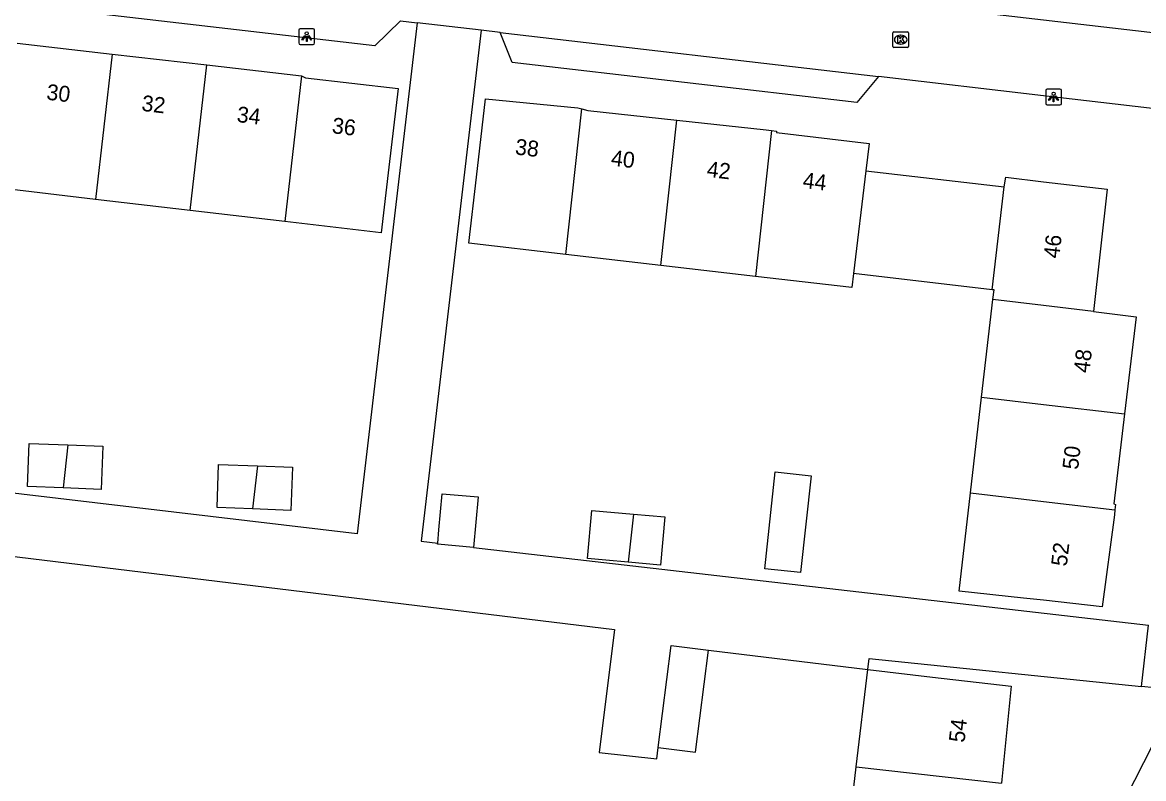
# Model space of a CAD drawing. Extents: x 161243 to 161752, y 384138 to 384885.
# Drawn here: x 161435.4 to 161506.3, y 384369.4 to 384417.2 of the extents above; entities that cross this region are included whole.
import ezdxf

# ---------------------------------------------------------------- set-up
doc = ezdxf.new("R2010")
doc.units = 0
for name, color, linetype in [('IMGEO_Kolk', 7, 'Continuous'), ('IMGEO_Lichtpunt', 7, 'Continuous'), ('IMGEO_Pand', 7, 'Continuous'), ('IMGEO_Pand_nummerreeks', 7, 'Continuous'), ('IMGEO_Parkeervlak_open', 7, 'Continuous'), ('IMGEO_Rijbaan_lokaal_open', 7, 'Continuous')]:
    doc.layers.add(name, color=color, linetype=linetype)

msp = doc.modelspace()

# ---------------------------------------------------------------- linework, layer by layer
at = {"layer": 'IMGEO_Kolk'}
for p, q in [((161490.463, 384415.656), (161490.463, 384416.508)), ((161490.538, 384416.582), (161491.39, 384416.582)), ((161490.951, 384416.362), (161490.976, 384416.362)), ((161491.464, 384416.508), (161491.464, 384415.656)), ((161491.39, 384415.582), (161490.538, 384415.582)), ((161490.974, 384415.802), (161490.949, 384415.802))]:
    msp.add_line(p, q, dxfattribs=at)
for points in [[(161490.463, 384415.656), (161490.463, 384416.508)], [(161490.538, 384416.582), (161491.39, 384416.582)], [(161490.784, 384416.282), (161490.907, 384416.282), (161490.907, 384416.131), (161491.037, 384416.282), (161491.201, 384416.282), (161491.055, 384416.131), (161491.208, 384415.882), (161491.056, 384415.882), (161490.971, 384416.046), (161490.907, 384415.979), (161490.907, 384415.882), (161490.784, 384415.882), (161490.784, 384416.282)], [(161491.464, 384416.508), (161491.464, 384415.656)], [(161491.39, 384415.582), (161490.538, 384415.582)]]:
    msp.add_lwpolyline(points, dxfattribs=at)
for centre, start, end in [((161490.54, 384416.506), 91.55205, 178.44795), ((161490.54, 384416.506), 91.55205, 178.44795), ((161491.388, 384416.506), 1.55205, 88.44795), ((161491.388, 384416.506), 1.55205, 88.44795), ((161490.54, 384415.658), 181.55205, 268.44795), ((161490.54, 384415.658), 181.55205, 268.44795), ((161491.388, 384415.658), 271.55205, 358.44795), ((161491.388, 384415.658), 271.55205, 358.44795)]:
    msp.add_arc(centre, 0.0765, start, end, dxfattribs=at)
for centre, major_axis, ratio, start_param, end_param in [((161490.95, 384416.082), (-0.387, 0.002), 0.722429, 4.712389, 7.853982), ((161490.975, 384416.082), (-0.39, 0.002), 0.717154, 1.570796, 4.712389)]:
    msp.add_ellipse(centre, major_axis=major_axis, ratio=ratio, start_param=start_param, end_param=end_param, dxfattribs=at)
at = {"layer": 'IMGEO_Lichtpunt'}
for p, q in [((161452.912, 384416.677), (161452.912, 384415.87)), ((161452.912, 384416.677), (161452.912, 384415.87)), ((161453.814, 384416.772), (161453.006, 384416.772)), ((161453.814, 384416.772), (161453.006, 384416.772)), ((161453.908, 384415.87), (161453.908, 384416.677)), ((161453.908, 384415.87), (161453.908, 384416.677)), ((161453.006, 384415.776), (161453.814, 384415.776)), ((161453.006, 384415.776), (161453.814, 384415.776)), ((161500.13, 384412.863), (161500.13, 384412.056)), ((161500.13, 384412.863), (161500.13, 384412.056)), ((161501.032, 384412.958), (161500.224, 384412.958)), ((161501.032, 384412.958), (161500.224, 384412.958)), ((161501.126, 384412.056), (161501.126, 384412.863)), ((161501.126, 384412.056), (161501.126, 384412.863)), ((161500.224, 384411.962), (161501.032, 384411.962)), ((161500.224, 384411.962), (161501.032, 384411.962))]:
    msp.add_line(p, q, dxfattribs=at)
for points in [[(161453.286, 384416.341), (161453.325, 384416.313), (161453.137, 384416.051), (161453.099, 384416.078), (161453.286, 384416.341)], [(161453.388, 384416.293), (161453.435, 384416.293), (161453.435, 384415.971), (161453.388, 384415.971), (161453.388, 384416.293)], [(161453.498, 384416.313), (161453.536, 384416.34), (161453.723, 384416.078), (161453.684, 384416.05), (161453.498, 384416.313)], [(161500.504, 384412.527), (161500.543, 384412.499), (161500.355, 384412.237), (161500.317, 384412.264), (161500.504, 384412.527)], [(161500.606, 384412.479), (161500.653, 384412.479), (161500.653, 384412.157), (161500.606, 384412.157), (161500.606, 384412.479)], [(161500.716, 384412.499), (161500.754, 384412.526), (161500.941, 384412.264), (161500.902, 384412.236), (161500.716, 384412.499)]]:
    msp.add_lwpolyline(points, dxfattribs=at)
for centre in [(161453.411, 384416.475), (161500.629, 384412.661)]:
    msp.add_circle(centre, 0.0994, dxfattribs=at)
for centre, start, end in [((161453.006, 384416.677), 90, 180), ((161453.006, 384416.677), 90, 180), ((161453.814, 384416.677), 0, 90), ((161453.814, 384416.677), 0, 90), ((161453.006, 384415.87), 180, 270), ((161453.006, 384415.87), 180, 270), ((161453.814, 384415.87), 270, 0), ((161453.814, 384415.87), 270, 360), ((161500.224, 384412.863), 90, 180), ((161500.224, 384412.863), 90, 180), ((161501.032, 384412.863), 0, 90), ((161501.032, 384412.863), 0, 90), ((161500.224, 384412.056), 180, 270), ((161500.224, 384412.056), 180, 270), ((161501.032, 384412.056), 270, 0), ((161501.032, 384412.056), 270, 360)]:
    msp.add_arc(centre, 0.0946, start, end, dxfattribs=at)
at = {"layer": 'IMGEO_Pand'}
for points in [[(161435.115, 384415.86), (161441.102, 384415.173)], [(161441.102, 384415.173), (161440.066, 384405.987)], [(161441.102, 384415.173), (161447.09, 384414.487)], [(161446.052, 384405.284), (161447.09, 384414.487)], [(161447.09, 384414.487), (161453.078, 384413.8)], [(161453.078, 384413.8), (161453.34, 384413.677), (161459.187, 384412.985), (161458.605, 384408.02), (161458.118, 384403.868), (161452.038, 384404.582)], [(161453.078, 384413.8), (161452.038, 384404.582)], [(161469.798, 384402.515), (161463.655, 384403.231), (161464.139, 384407.383), (161464.717, 384412.349), (161470.544, 384411.783), (161470.805, 384411.713)], [(161469.798, 384402.515), (161470.805, 384411.713)], [(161470.805, 384411.713), (161471.188, 384411.61), (161476.802, 384411.001)], [(161475.795, 384401.817), (161476.802, 384411.001)], [(161476.802, 384411.001), (161482.46, 384410.387), (161482.803, 384410.344)], [(161482.803, 384410.344), (161481.793, 384401.118)], [(161482.803, 384410.344), (161483.105, 384410.307), (161483.102, 384410.205), (161488.967, 384409.525), (161488.755, 384407.787)], [(161488.755, 384407.787), (161487.973, 384401.305)], [(161488.755, 384407.787), (161497.514, 384406.788)], [(161497.514, 384406.788), (161497.619, 384407.389), (161500, 384407.107), (161504.018, 384406.63), (161503.145, 384398.895)], [(161440.066, 384405.987), (161434.08, 384406.689)], [(161496.756, 384400.282), (161497.514, 384406.788)], [(161446.052, 384405.284), (161440.066, 384405.987)], [(161452.038, 384404.582), (161446.052, 384405.284)], [(161475.795, 384401.817), (161469.798, 384402.515)], [(161481.793, 384401.118), (161475.795, 384401.817)], [(161487.973, 384401.305), (161487.865, 384400.411), (161481.793, 384401.118)], [(161496.756, 384400.282), (161487.973, 384401.305)], [(161496.797, 384399.672), (161496.867, 384400.269), (161496.756, 384400.282)], [(161496.077, 384393.488), (161496.797, 384399.672)], [(161503.145, 384398.895), (161500, 384399.28), (161496.797, 384399.672)], [(161503.145, 384398.895), (161505.841, 384398.564), (161505.109, 384392.428)], [(161495.373, 384387.444), (161496.077, 384393.488)], [(161496.077, 384393.488), (161500, 384393.028), (161505.109, 384392.428)], [(161505.109, 384392.428), (161504.432, 384386.748), (161504.548, 384386.711), (161504.511, 384386.373)], [(161438.007, 384387.754), (161435.762, 384387.838), (161435.863, 384390.564), (161438.314, 384390.473)], [(161438.314, 384390.473), (161440.527, 384390.391), (161440.426, 384387.665), (161438.007, 384387.754)], [(161438.314, 384390.473), (161438.007, 384387.754)], [(161449.988, 384386.426), (161447.743, 384386.51), (161447.844, 384389.236), (161450.295, 384389.145)], [(161450.295, 384389.145), (161452.508, 384389.063), (161452.407, 384386.337), (161449.988, 384386.426)], [(161450.295, 384389.145), (161449.988, 384386.426)], [(161485.299, 384388.52), (161484.639, 384382.41), (161482.368, 384382.655), (161483.027, 384388.765), (161485.299, 384388.52)], [(161461.694, 384384.264), (161461.77, 384385.111), (161461.973, 384387.389), (161464.245, 384387.187), (161463.961, 384384)], [(161504.511, 384386.373), (161504.477, 384386.063), (161503.703, 384380.248), (161500, 384380.659), (161498.734, 384380.8), (161494.65, 384381.238), (161495.373, 384387.444)], [(161495.373, 384387.444), (161500, 384386.902), (161504.511, 384386.373)], [(161473.741, 384383.065), (161472.319, 384383.192), (161471.161, 384383.295), (161471.431, 384386.332), (161474.073, 384386.097)], [(161474.073, 384386.097), (161476.042, 384385.922), (161475.773, 384382.885), (161473.741, 384383.065)], [(161474.073, 384386.097), (161473.741, 384383.065)], [(161463.961, 384384), (161461.689, 384384.202), (161461.694, 384384.264)], [(161475.632, 384371.357), (161476.445, 384377.795), (161478.805, 384377.496)], [(161475.632, 384371.357), (161477.992, 384371.059), (161478.805, 384377.496)], [(161488.158, 384370.128), (161488.879, 384376.277)], [(161488.879, 384376.277), (161492.977, 384375.8), (161497.943, 384375.221), (161497.358, 384369.338), (161497.328, 384369.093)], [(161487.449, 384364.089), (161488.158, 384370.128)], [(161488.158, 384370.128), (161497.328, 384369.093)]]:
    msp.add_lwpolyline(points, dxfattribs=at)
at = {"layer": 'IMGEO_Parkeervlak_open'}
for points in [[(161459.347, 384417.271), (161457.727, 384415.687), (161417.974, 384420.297), (161417.282, 384422.167)], [(161489.559, 384413.756), (161488.192, 384412.116), (161466.402, 384414.639), (161465.637, 384416.532)], [(161496.955, 384351.974), (161500, 384357.957), (161508.657, 384374.966)]]:
    msp.add_lwpolyline(points, dxfattribs=at)
at = {"layer": 'IMGEO_Rijbaan_lokaal_open'}
for points in [[(161455.361, 384422.51), (161500, 384417.331), (161516.896, 384415.376)], [(161460.391, 384417.148), (161456.596, 384384.852), (161428.41, 384388.19)], [(161459.347, 384417.271), (161460.391, 384417.148)], [(161464.436, 384416.673), (161460.391, 384417.148)], [(161464.436, 384416.673), (161460.643, 384384.386), (161461.694, 384384.264)], [(161465.637, 384416.532), (161464.436, 384416.673)], [(161465.637, 384416.532), (161489.559, 384413.756)], [(161510.318, 384411.321), (161500, 384412.531), (161489.559, 384413.756)], [(161428.856, 384384.157), (161472.875, 384378.82), (161471.891, 384371.04), (161475.543, 384370.648), (161475.632, 384371.357)], [(161463.961, 384384), (161506.638, 384379.095)], [(161506.195, 384375.218), (161506.638, 384379.095)], [(161478.805, 384377.496), (161488.879, 384376.277)], [(161488.879, 384376.277), (161488.964, 384376.982), (161506.195, 384375.218)], [(161508.657, 384374.966), (161506.195, 384375.218)]]:
    msp.add_lwpolyline(points, dxfattribs=at)

# ---------------------------------------------------------------- texts
at = {"layer": 'IMGEO_Pand_nummerreeks'}
for s, rotation, p in [('30', 353.30595, (161436.925, 384412.295)), ('32', 353.30595, (161442.937, 384411.589)), ('34', 353.30595, (161448.957, 384410.883)), ('36', 353.30595, (161454.975, 384410.177)), ('38', 353.35762, (161466.551, 384408.833)), ('40', 353.35762, (161472.613, 384408.127)), ('42', 353.35762, (161478.67, 384407.421)), ('44', 353.35942, (161484.735, 384406.715)), ('46', 83.56064, (161500.985, 384402.224)), ('48', 83.34208, (161502.886, 384394.986)), ('50', 83.34208, (161502.174, 384388.88)), ('52', 83.34208, (161501.46, 384382.769)), ('54', 83.41556, (161494.993, 384371.636))]:
    msp.add_text(s, height=1, rotation=rotation, dxfattribs=at).set_placement(p)

doc.saveas('drawing.dxf')
